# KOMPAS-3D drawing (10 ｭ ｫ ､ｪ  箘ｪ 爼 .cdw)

Referenced files: Чертеж эскиз.cdw
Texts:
  ТМ-27А.КП.
  Карта наладки
  Текст на чертеже
  Размерные надписи
  Шероховатость
  Линия-выноска #1
  Линия-выноска #2
  Линия-выноска #3
  Отклонения формы и база
  Заголовок таблицы
  Ячейка таблицы
  Стрелка вида
  Обозначение изменения
  Фигурная скобка
  Номер узла
  Марка координационной оси
  VRCB
  Выносная надпись
  Обозначение узла
  Марка/позиционное обозначение с линией-выноской
  Марка/позиционное обозначение на линии
  Марка/позиционное обозначение без линии-выноски
  СК 1
  Операция 015 Токарная
  Установ А
  Циклограмма движения инструмента
  РХ1
  РХ2
  РХ3
  РХ4
  РХ5
  РХ6
  Центр вращающийся
  Dsп
  Dsпр
  Резец упорный Т5К10
  по ГОСТ 18870-73
  Патрон поводковый
  и модель
  оборудования
  инструмента
  So,
  мм/об
  м/мин
  об/мин
  мм/мин
  Тo,
  мин
  Тшк,
  Ra 12,5
  Технологический процесс
  изготавления первичного вала
  НТУ "ХПИ"
  каф. АиТ
  Павлий
  ТМ-27.КП.12.6.0911.03.-
Dimensions and other numbers on the sheet: 7; 231,5; 78; 31; 16К20Ф3; 1; 1,5; 0,4; 75,4; 800; 0,83; 4,27; 1:1; 0; 2; 3; 4; 5; 6; 8; 9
